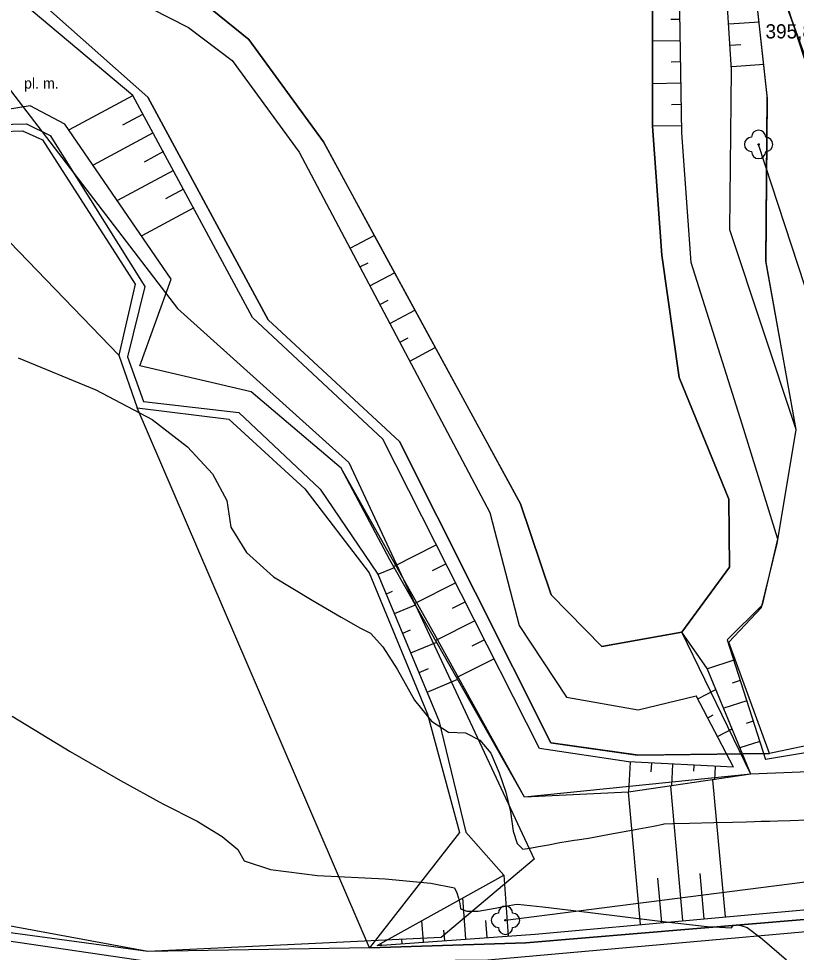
# Model space of a CAD drawing. Extents: x -574342 to -508101, y -1143544 to -1123894.
# Drawn here: x -508505.5 to -508450.7, y -1143258.4 to -1143192.6 of the extents above; entities that cross this region are included whole.
import ezdxf

# ---------------------------------------------------------------- set-up
doc = ezdxf.new("R2010")
doc.units = 0
for name, color, linetype in [('01_PARCELY_NAVRH_PC', 7, 'Continuous'), ('01_PARCELY_NAVRH_VHO', 7, 'Continuous'), ('01_PARCELY_NAVRH_ŽP', 7, 'Continuous'), ('05_VHO_V_NÁDRŽ_STAV', 7, 'Continuous'), ('05_VHO_V_TOK_STAV', 7, 'Continuous'), ('16', 7, 'Continuous'), ('37', 7, 'Continuous'), ('42', 7, 'Continuous'), ('51', 7, 'Continuous'), ('54', 7, 'Continuous'), ('55', 7, 'Continuous'), ('60', 7, 'Continuous'), ('61', 7, 'Continuous'), ('Level 255', 7, 'Continuous'), ('VRST VEDL', 7, 'Continuous')]:
    doc.layers.add(name, color=color, linetype=linetype)

msp = doc.modelspace()

# ---------------------------------------------------------------- linework, layer by layer
at = {"layer": '01_PARCELY_NAVRH_PC'}
msp.add_lwpolyline([(-508445.99, -1143206.42), (-508454.33, -1143183.49), (-508456.87, -1143173.84), (-508463.3, -1143163.03), (-508476.26, -1143134.7), (-508479.46, -1143126.74), (-508474.05, -1143124.14), (-508467.92, -1143139.18), (-508459.97, -1143152.33), (-508456.09, -1143158.71), (-508451.57, -1143168.14), (-508437.66, -1143207.58)], dxfattribs=at)
msp.add_lwpolyline([(-508446.21, -1143255.76), (-508469.74, -1143257.73), (-508480.76, -1143258.08), (-508496.39, -1143258.35), (-508520.28, -1143255.11), (-508526.55, -1143254.9), (-508531.16, -1143250.06), (-508524.26, -1143263.08), (-508521.01, -1143259.29), (-508514.56, -1143259.91), (-508493.5, -1143263.3), (-508475.11, -1143263.39), (-508446.02, -1143260.22)], close=True, dxfattribs=at)
at = {"layer": '01_PARCELY_NAVRH_VHO'}
for points in [[(-508446.56, -1143243.12), (-508452.58, -1143244.39), (-508461.81, -1143244.49), (-508467.98, -1143243.62), (-508478.66, -1143222.38), (-508487.9, -1143213.8), (-508496.38, -1143198.1), (-508504.26, -1143191.1), (-508516.39, -1143188), (-508530.07, -1143174.68), (-508539.86, -1143167.27), (-508547.02, -1143163.34), (-508553.27, -1143164.53), (-508559.77, -1143166.35), (-508565.39, -1143163.91), (-508571.39, -1143166.22), (-508578.23, -1143159.53), (-508587.9, -1143163.05), (-508596.45, -1143153.64), (-508600.04, -1143155.89), (-508608.16, -1143150.99), (-508613.1, -1143145.09)], [(-508551.68, -1143170.14), (-508549.4, -1143169.86), (-508545.04, -1143171.57), (-508537.18, -1143176.51), (-508534.6, -1143178.15), (-508533.13, -1143181.54), (-508526.17, -1143187.6), (-508523.49, -1143191.39), (-508517.97, -1143196.35), (-508514.48, -1143199.68), (-508508.1, -1143200.58), (-508505.21, -1143200.49), (-508503.8, -1143201.12), (-508497.27, -1143211.29), (-508498.42, -1143216.3), (-508497.14, -1143220.02), (-508490.67, -1143220.8), (-508485.31, -1143225.73), (-508480.78, -1143231.64), (-508476.67, -1143241.6), (-508474.42, -1143249.95), (-508480.76, -1143258.08), (-508469.74, -1143257.73), (-508446.21, -1143255.76)], [(-508504.26, -1143191.1), (-508496.38, -1143198.1), (-508487.9, -1143213.8), (-508478.66, -1143222.38), (-508467.98, -1143243.62), (-508461.87, -1143244.49), (-508452.58, -1143244.39), (-508455.43, -1143236.54), (-508453.14, -1143234.1), (-508452.04, -1143229.57), (-508450.69, -1143221.56), (-508452.8, -1143209.75), (-508452.72, -1143198.2), (-508454.33, -1143183.49)]]:
    msp.add_lwpolyline(points, dxfattribs=at)
at = {"layer": '01_PARCELY_NAVRH_ŽP'}
for points in [[(-508455.43, -1143236.54), (-508453.14, -1143234.1), (-508452.04, -1143229.57), (-508450.69, -1143221.56), (-508452.8, -1143209.75), (-508452.72, -1143198.2), (-508454.33, -1143183.49), (-508445.99, -1143206.42), (-508432.73, -1143240.34), (-508433.72, -1143240.11), (-508438.05, -1143241.09), (-508444.11, -1143244.2), (-508446.56, -1143243.12), (-508452.58, -1143244.39)], [(-508498.42, -1143216.3), (-508514.48, -1143199.68), (-508508.1, -1143200.58), (-508505.21, -1143200.49), (-508503.8, -1143201.12), (-508497.27, -1143211.29)], [(-508480.76, -1143258.08), (-508497.14, -1143220.02), (-508490.67, -1143220.8), (-508485.31, -1143225.73), (-508480.78, -1143231.64), (-508476.67, -1143241.6), (-508474.42, -1143249.95)]]:
    msp.add_lwpolyline(points, close=True, dxfattribs=at)
at = {"layer": '05_VHO_V_NÁDRŽ_STAV'}
msp.add_lwpolyline([(-508492.34, -1143191.56), (-508489.27, -1143194.04), (-508484.01, -1143201.26), (-508480.426, -1143207.853), (-508478.993, -1143210.489), (-508477.56, -1143213.124), (-508476.127, -1143215.76), (-508470.13, -1143226.79), (-508467.96, -1143233.2), (-508464.38, -1143236.85), (-508458.75, -1143235.83), (-508455.39, -1143231.25), (-508455.44, -1143226.46), (-508458.93, -1143217.88), (-508460.15, -1143209.24), (-508460.83, -1143200.16), (-508460.83, -1143197.16), (-508460.83, -1143194.159), (-508460.83, -1143190.06)], dxfattribs=at)
at = {"layer": '05_VHO_V_TOK_STAV'}
msp.add_line((-508453.89, -1143245.84), (-508458.75, -1143235.83), dxfattribs=at)
msp.add_lwpolyline([(-508447.49, -1143245.57), (-508453.89, -1143245.84), (-508469.84, -1143247.46), (-508476.067, -1143236.175), (-508482.77, -1143224.26), (-508489.11, -1143218.88), (-508496.94, -1143217.04), (-508494.75, -1143210.95), (-508502.24, -1143200.02), (-508504.69, -1143198.72), (-508508.04, -1143199.26), (-508513.72, -1143198.12), (-508516.16, -1143196.14), (-508515.31, -1143194.32), (-508517.287, -1143192.866), (-508519.733, -1143191.098), (-508522.24, -1143189.31), (-508524.27, -1143185.62), (-508530.674, -1143178.031), (-508542.01, -1143169.37), (-508547.92, -1143166.82), (-508560.33, -1143168.91)], dxfattribs=at)
at = {"layer": '37'}
for points in [[(-508453.89, -1143245.84), (-508462.52, -1143247.11), (-508469.84, -1143247.46), (-508479.32, -1143230.73), (-508482.77, -1143224.26), (-508489.11, -1143218.88), (-508496.94, -1143217.04), (-508494.75, -1143210.95), (-508502.24, -1143200.02), (-508504.69, -1143198.72), (-508508.04, -1143199.26), (-508513.72, -1143198.12), (-508516.16, -1143196.14), (-508515.31, -1143194.32), (-508522.24, -1143189.31), (-508524.27, -1143185.62), (-508530.09, -1143178.84), (-508531.6, -1143177.56), (-508524.5, -1143179.18), (-508517.75, -1143180.38), (-508509.75, -1143181.27)], [(-508453.89, -1143245.84), (-508462.52, -1143247.11), (-508469.84, -1143247.46), (-508479.32, -1143230.73), (-508482.77, -1143224.26), (-508489.11, -1143218.88), (-508496.94, -1143217.04), (-508494.75, -1143210.95), (-508502.24, -1143200.02), (-508504.69, -1143198.72), (-508508.04, -1143199.26), (-508513.72, -1143198.12), (-508516.16, -1143196.14), (-508515.31, -1143194.32), (-508522.24, -1143189.31), (-508524.27, -1143185.62), (-508530.09, -1143178.84), (-508531.6, -1143177.56), (-508524.5, -1143179.18), (-508517.75, -1143180.38), (-508509.75, -1143181.27)], [(-508442.91, -1143250.47), (-508445.36, -1143246.6), (-508447.49, -1143245.57), (-508453.89, -1143245.84), (-508456.96, -1143238.4), (-508458.75, -1143235.83)], [(-508442.91, -1143250.47), (-508445.36, -1143246.6), (-508447.49, -1143245.57), (-508453.89, -1143245.84), (-508456.96, -1143238.4), (-508458.75, -1143235.83)]]:
    msp.add_lwpolyline(points, dxfattribs=at)
at = {"layer": '42'}
for points in [[(-508538.33, -1143193.52), (-508529.17, -1143180.12), (-508522.42, -1143187.78), (-508506.94, -1143196.54), (-508494.29, -1143213), (-508482.23, -1143223.86), (-508469.17, -1143251.83), (-508475.71, -1143257.35)], [(-508538.33, -1143193.52), (-508529.17, -1143180.12), (-508522.42, -1143187.78), (-508506.94, -1143196.54), (-508494.29, -1143213), (-508482.23, -1143223.86), (-508469.17, -1143251.83), (-508475.71, -1143257.35)], [(-508475.71, -1143257.35), (-508496.39, -1143258.35), (-508520.72, -1143253.86), (-508528.66, -1143251.18), (-508534.38, -1143238.75), (-508538.15, -1143218.95), (-508538.33, -1143193.52)], [(-508475.71, -1143257.35), (-508496.39, -1143258.35), (-508520.72, -1143253.86), (-508528.66, -1143251.18), (-508534.38, -1143238.75), (-508538.15, -1143218.95), (-508538.33, -1143193.52)]]:
    msp.add_lwpolyline(points, dxfattribs=at)
at = {"layer": '51'}
msp.add_lwpolyline([(-508460.83, -1143190.06), (-508460.83, -1143200.16), (-508460.15, -1143209.24), (-508458.93, -1143217.88), (-508455.44, -1143226.46), (-508455.39, -1143231.25), (-508458.75, -1143235.83), (-508464.38, -1143236.85), (-508467.96, -1143233.2), (-508470.13, -1143226.79), (-508484.01, -1143201.26), (-508489.27, -1143194.04), (-508492.34, -1143191.56)], dxfattribs=at)
msp.add_lwpolyline([(-508460.83, -1143190.06), (-508460.83, -1143200.16), (-508460.15, -1143209.24), (-508458.93, -1143217.88), (-508455.44, -1143226.46), (-508455.39, -1143231.25), (-508458.75, -1143235.83), (-508464.38, -1143236.85), (-508467.96, -1143233.2), (-508470.13, -1143226.79), (-508484.01, -1143201.26), (-508489.27, -1143194.04), (-508492.34, -1143191.56)], dxfattribs=at)
at = {"layer": '54'}
for centre in [(-508453.34, -1143201.44), (-508471.18, -1143256.14)]:
    msp.add_circle(centre, 0.05, dxfattribs=at)
for centre, start, end in [((-508453.34, -1143200.94), 0, 180), ((-508453.84, -1143201.44), 90, 270), ((-508452.84, -1143201.44), 270, 90), ((-508453.34, -1143201.94), 180, 0), ((-508471.18, -1143255.64), 0, 180), ((-508471.68, -1143256.14), 90, 270), ((-508470.68, -1143256.14), 270, 90), ((-508471.18, -1143256.64), 180, 0)]:
    msp.add_arc(centre, 0.5, start, end, dxfattribs=at)
at = {"layer": '55'}
msp.add_line((-508438.93, -1143245.61), (-508453.34, -1143201.44), dxfattribs=at)
msp.add_line((-508438.93, -1143245.61), (-508453.34, -1143201.44), dxfattribs=at)
for points in [[(-508435.13, -1143235.61), (-508444.83, -1143211.72), (-508456.61, -1143175.27)], [(-508435.13, -1143235.61), (-508444.83, -1143211.72), (-508456.61, -1143175.27)], [(-508471.18, -1143256.14), (-508439.22, -1143252.04), (-508433.46, -1143242.87)], [(-508471.18, -1143256.14), (-508439.22, -1143252.04), (-508433.46, -1143242.87)], [(-508495.48, -1143259.17), (-508472.43, -1143258.93), (-508435.48, -1143255.63), (-508431.4, -1143253.75), (-508428.49, -1143248.11)], [(-508495.48, -1143259.17), (-508472.43, -1143258.93), (-508435.48, -1143255.63), (-508431.4, -1143253.75), (-508428.49, -1143248.11)], [(-508530.09, -1143253.58), (-508526.75, -1143255.23), (-508519.02, -1143255.71), (-508495.48, -1143259.17)], [(-508530.09, -1143253.58), (-508526.75, -1143255.23), (-508519.02, -1143255.71), (-508495.48, -1143259.17)]]:
    msp.add_lwpolyline(points, dxfattribs=at)
at = {"layer": '60'}
for p, q in [((-508455.56, -1143236.37), (-508452.85, -1143244.81)), ((-508455.56, -1143236.37), (-508452.85, -1143244.81)), ((-508455.11, -1143245.35), (-508457.74, -1143240.31)), ((-508455.11, -1143245.35), (-508457.74, -1143240.31)), ((-508480.22, -1143257.91), (-508471.29, -1143252.95)), ((-508480.22, -1143257.91), (-508471.29, -1143252.95))]:
    msp.add_line(p, q, dxfattribs=at)
for points in [[(-508455.56, -1143236.37), (-508453.06, -1143233.89), (-508451.99, -1143229.27), (-508454.51, -1143221.16), (-508458.09, -1143209.77), (-508458.76, -1143200.63), (-508458.93, -1143189.23), (-508462.08, -1143179.93), (-508467.63, -1143168.34), (-508471.31, -1143163.81), (-508477.14, -1143162.33), (-508483.91, -1143163.18), (-508491.81, -1143167.17), (-508499.86, -1143173.8), (-508502.62, -1143178.78)], [(-508455.56, -1143236.37), (-508453.06, -1143233.89), (-508451.99, -1143229.27), (-508454.51, -1143221.16), (-508458.09, -1143209.77), (-508458.76, -1143200.63), (-508458.93, -1143189.23), (-508462.08, -1143179.93), (-508467.63, -1143168.34), (-508471.31, -1143163.81), (-508477.14, -1143162.33), (-508483.91, -1143163.18), (-508491.81, -1143167.17), (-508499.86, -1143173.8), (-508502.62, -1143178.78)], [(-508450.7, -1143221.55), (-508452.82, -1143209.68), (-508452.74, -1143198.02), (-508454.33, -1143183.49), (-508457.05, -1143173.57)], [(-508450.7, -1143221.55), (-508452.82, -1143209.68), (-508452.74, -1143198.02), (-508454.33, -1143183.49), (-508457.05, -1143173.57)], [(-508525.16, -1143176.55), (-508530.6, -1143175.07), (-508532.55, -1143176.28), (-508533.83, -1143178.28), (-508532.4, -1143181.41), (-508525.65, -1143187.42), (-508523.14, -1143191), (-508516.45, -1143194.78), (-508517.33, -1143196.24), (-508514.08, -1143199.23), (-508507.94, -1143200.06), (-508504.93, -1143199.98), (-508503.26, -1143200.81), (-508496.6, -1143211.46), (-508497.83, -1143216.41), (-508496.7, -1143219.56), (-508489.97, -1143220.34), (-508484.25, -1143225.74), (-508480.17, -1143231.74), (-508475.87, -1143242.05), (-508473.98, -1143249.93), (-508471.29, -1143252.95)], [(-508525.16, -1143176.55), (-508530.6, -1143175.07), (-508532.55, -1143176.28), (-508533.83, -1143178.28), (-508532.4, -1143181.41), (-508525.65, -1143187.42), (-508523.14, -1143191), (-508516.45, -1143194.78), (-508517.33, -1143196.24), (-508514.08, -1143199.23), (-508507.94, -1143200.06), (-508504.93, -1143199.98), (-508503.26, -1143200.81), (-508496.6, -1143211.46), (-508497.83, -1143216.41), (-508496.7, -1143219.56), (-508489.97, -1143220.34), (-508484.25, -1143225.74), (-508480.17, -1143231.74), (-508475.87, -1143242.05), (-508473.98, -1143249.93), (-508471.29, -1143252.95)], [(-508450.7, -1143221.55), (-508455.37, -1143207.46), (-508455.25, -1143196.19), (-508455.84, -1143186.95), (-508460.82, -1143174.63)], [(-508450.7, -1143221.55), (-508455.37, -1143207.46), (-508455.25, -1143196.19), (-508455.84, -1143186.95), (-508460.82, -1143174.63)], [(-508502.62, -1143178.78), (-508502.72, -1143182.77), (-508502.79, -1143186.19), (-508500.02, -1143189.86), (-508493.53, -1143193.19), (-508490.45, -1143195.53), (-508485.71, -1143201.99), (-508472.29, -1143227.39), (-508470.21, -1143235.36), (-508466.87, -1143240.4), (-508461.84, -1143241.3), (-508457.74, -1143240.31)], [(-508502.62, -1143178.78), (-508502.72, -1143182.77), (-508502.79, -1143186.19), (-508500.02, -1143189.86), (-508493.53, -1143193.19), (-508490.45, -1143195.53), (-508485.71, -1143201.99), (-508472.29, -1143227.39), (-508470.21, -1143235.36), (-508466.87, -1143240.4), (-508461.84, -1143241.3), (-508457.74, -1143240.31)], [(-508455.11, -1143245.35), (-508462.52, -1143244.98), (-508468.78, -1143244.04), (-508479.83, -1143222.21), (-508489, -1143213.65), (-508497.45, -1143197.99), (-508505.2, -1143191.49), (-508517.74, -1143188.22), (-508526.49, -1143181.14), (-508518.79, -1143183), (-508509.43, -1143184.84)], [(-508455.11, -1143245.35), (-508462.52, -1143244.98), (-508468.78, -1143244.04), (-508479.83, -1143222.21), (-508489, -1143213.65), (-508497.45, -1143197.99), (-508505.2, -1143191.49), (-508517.74, -1143188.22), (-508526.49, -1143181.14), (-508518.79, -1143183), (-508509.43, -1143184.84)], [(-508480.22, -1143257.91), (-508469.09, -1143257.11), (-508446.3, -1143255.05), (-508439.65, -1143253.6), (-508441.71, -1143248.16), (-508443.77, -1143245.44), (-508437.62, -1143242.68), (-508434.01, -1143242.01), (-508430.69, -1143242.47), (-508430.86, -1143241.32), (-508433.93, -1143240.67), (-508438.09, -1143241.68), (-508444.43, -1143244.81), (-508446.95, -1143243.83), (-508452.85, -1143244.81)], [(-508480.22, -1143257.91), (-508469.09, -1143257.11), (-508446.3, -1143255.05), (-508439.65, -1143253.6), (-508441.71, -1143248.16), (-508443.77, -1143245.44), (-508437.62, -1143242.68), (-508434.01, -1143242.01), (-508430.69, -1143242.47), (-508430.86, -1143241.32), (-508433.93, -1143240.67), (-508438.09, -1143241.68), (-508444.43, -1143244.81), (-508446.95, -1143243.83), (-508452.85, -1143244.81)]]:
    msp.add_lwpolyline(points, dxfattribs=at)
at = {"layer": '61'}
for p, q in [((-508458.879, -1143192.63), (-508459.529, -1143192.64)), ((-508458.879, -1143192.63), (-508459.529, -1143192.64)), ((-508455.431, -1143192.947), (-508453.281, -1143192.808)), ((-508455.431, -1143192.947), (-508453.281, -1143192.808)), ((-508458.857, -1143194.13), (-508460.83, -1143194.159)), ((-508458.857, -1143194.13), (-508460.83, -1143194.159)), ((-508455.334, -1143194.444), (-508454.596, -1143194.396)), ((-508455.334, -1143194.444), (-508454.596, -1143194.396)), ((-508458.835, -1143195.63), (-508459.499, -1143195.64)), ((-508458.835, -1143195.63), (-508459.499, -1143195.64)), ((-508455.237, -1143195.941), (-508452.955, -1143195.793)), ((-508455.237, -1143195.941), (-508452.955, -1143195.793)), ((-508458.812, -1143197.13), (-508460.83, -1143197.16)), ((-508458.812, -1143197.13), (-508460.83, -1143197.16)), ((-508497.43, -1143197.99), (-508501.934, -1143200.423)), ((-508497.43, -1143197.99), (-508501.934, -1143200.423)), ((-508458.79, -1143198.629), (-508459.469, -1143198.64)), ((-508458.79, -1143198.629), (-508459.469, -1143198.64)), ((-508496.717, -1143199.31), (-508498.17, -1143200.095)), ((-508496.717, -1143199.31), (-508498.17, -1143200.095)), ((-508496.004, -1143200.629), (-508500.228, -1143202.912)), ((-508496.004, -1143200.629), (-508500.228, -1143202.912)), ((-508458.767, -1143200.129), (-508460.83, -1143200.16)), ((-508458.767, -1143200.129), (-508460.83, -1143200.16)), ((-508495.291, -1143201.949), (-508496.651, -1143202.684)), ((-508495.291, -1143201.949), (-508496.651, -1143202.684)), ((-508494.578, -1143203.269), (-508498.523, -1143205.4)), ((-508494.578, -1143203.269), (-508498.523, -1143205.4)), ((-508493.865, -1143204.589), (-508495.132, -1143205.273)), ((-508493.865, -1143204.589), (-508495.132, -1143205.273)), ((-508493.152, -1143205.908), (-508496.818, -1143207.889)), ((-508493.152, -1143205.908), (-508496.818, -1143207.889)), ((-508482.135, -1143208.756), (-508480.426, -1143207.853)), ((-508482.135, -1143208.756), (-508480.426, -1143207.853)), ((-508481.434, -1143210.082), (-508480.86, -1143209.779)), ((-508481.434, -1143210.082), (-508480.86, -1143209.779)), ((-508480.734, -1143211.409), (-508478.993, -1143210.489)), ((-508480.734, -1143211.409), (-508478.993, -1143210.489)), ((-508480.033, -1143212.735), (-508479.448, -1143212.426)), ((-508480.033, -1143212.735), (-508479.448, -1143212.426)), ((-508479.332, -1143214.061), (-508477.56, -1143213.124)), ((-508479.332, -1143214.061), (-508477.56, -1143213.124)), ((-508478.632, -1143215.387), (-508478.036, -1143215.073)), ((-508478.632, -1143215.387), (-508478.036, -1143215.073)), ((-508477.931, -1143216.714), (-508476.127, -1143215.76)), ((-508477.931, -1143216.714), (-508476.127, -1143215.76)), ((-508476.04, -1143229.667), (-508479.046, -1143231.189)), ((-508476.04, -1143229.667), (-508479.046, -1143231.189)), ((-508475.363, -1143231.005), (-508476.343, -1143231.502)), ((-508475.363, -1143231.005), (-508476.343, -1143231.502)), ((-508480.15, -1143231.74), (-508479.004, -1143231.263)), ((-508480.15, -1143231.74), (-508479.004, -1143231.263)), ((-508474.686, -1143232.344), (-508477.566, -1143233.802)), ((-508474.686, -1143232.344), (-508477.566, -1143233.802)), ((-508479.574, -1143233.125), (-508479.136, -1143232.943)), ((-508479.574, -1143233.125), (-508479.136, -1143232.943)), ((-508478.997, -1143234.51), (-508477.514, -1143233.893)), ((-508478.997, -1143234.51), (-508477.514, -1143233.893)), ((-508474.008, -1143233.682), (-508474.946, -1143234.157)), ((-508474.008, -1143233.682), (-508474.946, -1143234.157)), ((-508473.331, -1143235.02), (-508476.086, -1143236.415)), ((-508473.331, -1143235.02), (-508476.086, -1143236.415)), ((-508478.421, -1143235.895), (-508477.871, -1143235.666)), ((-508478.421, -1143235.895), (-508477.871, -1143235.666)), ((-508477.845, -1143237.28), (-508476.025, -1143236.522)), ((-508477.845, -1143237.28), (-508476.025, -1143236.522)), ((-508472.653, -1143236.359), (-508473.55, -1143236.813)), ((-508472.653, -1143236.359), (-508473.55, -1143236.813)), ((-508471.976, -1143237.697), (-508474.606, -1143239.028)), ((-508471.976, -1143237.697), (-508474.606, -1143239.028)), ((-508455.09, -1143237.813), (-508456.95, -1143238.41)), ((-508455.09, -1143237.813), (-508456.95, -1143238.41)), ((-508477.269, -1143238.664), (-508476.607, -1143238.389)), ((-508477.269, -1143238.664), (-508476.607, -1143238.389)), ((-508476.692, -1143240.049), (-508474.536, -1143239.152)), ((-508476.692, -1143240.049), (-508474.536, -1143239.152)), ((-508454.631, -1143239.241), (-508455.212, -1143239.427)), ((-508454.631, -1143239.241), (-508455.212, -1143239.427)), ((-508457.613, -1143240.527), (-508456.348, -1143239.869)), ((-508457.613, -1143240.527), (-508456.348, -1143239.869)), ((-508454.173, -1143240.669), (-508455.802, -1143241.192)), ((-508454.173, -1143240.669), (-508455.802, -1143241.192)), ((-508456.921, -1143241.858), (-508456.539, -1143241.659)), ((-508456.921, -1143241.858), (-508456.539, -1143241.659)), ((-508453.714, -1143242.097), (-508454.218, -1143242.259)), ((-508453.714, -1143242.097), (-508454.218, -1143242.259)), ((-508456.229, -1143243.189), (-508455.199, -1143242.653)), ((-508456.229, -1143243.189), (-508455.199, -1143242.653)), ((-508453.256, -1143243.525), (-508454.654, -1143243.974)), ((-508453.256, -1143243.525), (-508454.654, -1143243.974)), ((-508462.394, -1143244.995), (-508462.5, -1143247.12)), ((-508462.394, -1143244.995), (-508462.5, -1143247.12)), ((-508460.896, -1143245.07), (-508460.926, -1143245.679)), ((-508460.896, -1143245.07), (-508460.926, -1143245.679)), ((-508459.398, -1143245.145), (-508459.474, -1143246.674)), ((-508459.398, -1143245.145), (-508459.474, -1143246.674)), ((-508457.899, -1143245.22), (-508457.92, -1143245.63)), ((-508457.899, -1143245.22), (-508457.92, -1143245.63)), ((-508456.401, -1143245.295), (-508456.448, -1143246.228)), ((-508456.401, -1143245.295), (-508456.448, -1143246.228)), ((-508458.67, -1143256.168), (-508459.527, -1143246.682)), ((-508458.67, -1143256.168), (-508459.527, -1143246.682)), ((-508455.682, -1143255.898), (-508456.555, -1143246.244)), ((-508455.682, -1143255.898), (-508456.555, -1143246.244)), ((-508461.658, -1143256.438), (-508462.5, -1143247.12)), ((-508461.658, -1143256.438), (-508462.5, -1143247.12)), ((-508470.975, -1143257.244), (-508471.28, -1143252.95)), ((-508470.975, -1143257.244), (-508471.28, -1143252.95)), ((-508460.164, -1143256.303), (-508460.447, -1143253.172)), ((-508460.164, -1143256.303), (-508460.447, -1143253.172)), ((-508457.176, -1143256.033), (-508457.464, -1143252.846)), ((-508457.176, -1143256.033), (-508457.464, -1143252.846)), ((-508473.968, -1143257.456), (-508474.174, -1143254.552)), ((-508473.968, -1143257.456), (-508474.174, -1143254.552)), ((-508476.96, -1143257.669), (-508477.068, -1143256.155)), ((-508476.96, -1143257.669), (-508477.068, -1143256.155)), ((-508472.471, -1143257.35), (-508472.557, -1143256.152)), ((-508472.471, -1143257.35), (-508472.557, -1143256.152)), ((-508475.464, -1143257.562), (-508475.516, -1143256.827)), ((-508475.464, -1143257.562), (-508475.516, -1143256.827)), ((-508479.953, -1143257.881), (-508479.961, -1143257.757)), ((-508479.953, -1143257.881), (-508479.961, -1143257.757)), ((-508478.456, -1143257.775), (-508478.476, -1143257.502)), ((-508478.456, -1143257.775), (-508478.476, -1143257.502))]:
    msp.add_line(p, q, dxfattribs=at)
at = {"layer": 'VRST VEDL'}
for points in [[(-508505.52, -1143216.478), (-508500.057, -1143218.745), (-508496.081, -1143220.84), (-508493.592, -1143222.764), (-508491.837, -1143224.667), (-508490.814, -1143226.551), (-508490.525, -1143228.415), (-508489.428, -1143230.205), (-508487.524, -1143231.92), (-508484.811, -1143233.562), (-508482.77, -1143234.773), (-508481.399, -1143235.554), (-508480.7, -1143235.906), (-508479.834, -1143236.868), (-508478.802, -1143238.44), (-508477.602, -1143240.624), (-508476.4, -1143242.1), (-508475.197, -1143242.869), (-508473.991, -1143242.931), (-508472.993, -1143243.431), (-508472.201, -1143244.369), (-508471.615, -1143245.746), (-508471.16, -1143247.119), (-508470.836, -1143248.488), (-508470.641, -1143249.854), (-508470.346, -1143250.735), (-508469.951, -1143251.133), (-508469.456, -1143251.046), (-508468.858, -1143250.94), (-508468.159, -1143250.813), (-508467.358, -1143250.667), (-508466.751, -1143250.562), (-508466.337, -1143250.499), (-508466.116, -1143250.478), (-508465.328, -1143250.345), (-508463.973, -1143250.1), (-508462.05, -1143249.744), (-508460.746, -1143249.5), (-508460.059, -1143249.368), (-508459.991, -1143249.348), (-508459.376, -1143249.321), (-508458.215, -1143249.287), (-508456.507, -1143249.246), (-508455.174, -1143249.214), (-508454.214, -1143249.191), (-508453.628, -1143249.177), (-508453.156, -1143249.164), (-508452.798, -1143249.153), (-508452.555, -1143249.143), (-508451.993, -1143249.125), (-508451.113, -1143249.099), (-508449.914, -1143249.065)], [(-508505.958, -1143241.749), (-508501.854, -1143244.233), (-508498.309, -1143246.295), (-508495.324, -1143247.935), (-508492.899, -1143249.155), (-508491.137, -1143250.23), (-508490.04, -1143251.162), (-508489.607, -1143251.95), (-508487.735, -1143252.557), (-508484.423, -1143252.983), (-508479.671, -1143253.228), (-508476.451, -1143253.515), (-508474.762, -1143253.844), (-508474.604, -1143254.216), (-508474.481, -1143254.587), (-508474.394, -1143254.957), (-508474.341, -1143255.325), (-508473.91, -1143255.502), (-508473.1, -1143255.487), (-508471.911, -1143255.279), (-508471.053, -1143255.128), (-508470.526, -1143255.035), (-508470.33, -1143254.999), (-508468.557, -1143255.183), (-508465.209, -1143255.585), (-508460.285, -1143256.206), (-508456.965, -1143256.568), (-508455.247, -1143256.67), (-508455.134, -1143256.512), (-508454.913, -1143256.456), (-508454.586, -1143256.503), (-508454.152, -1143256.653), (-508453.08, -1143257.458), (-508451.371, -1143258.92)]]:
    msp.add_lwpolyline(points, dxfattribs=at)

# ---------------------------------------------------------------- texts
at = {"layer": '16'}
msp.add_text('pl. m.', height=0.75, dxfattribs=at).set_placement((-508505.115, -1143197.506))
at = {"layer": 'Level 255'}
msp.add_text('395,84', height=1, dxfattribs=at).set_placement((-508452.855, -1143193.97))

doc.saveas('drawing.dxf')
